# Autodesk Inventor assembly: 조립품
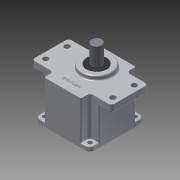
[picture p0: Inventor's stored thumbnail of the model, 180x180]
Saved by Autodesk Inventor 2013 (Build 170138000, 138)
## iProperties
Created: 2015-07
Part Number: 조립품
Document SubType Name: Assembly
Designer: user
Author: user
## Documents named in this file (12)
- C:\Users\user\Desktop\450734V1001\조립품.iam
- C:\Users\user\Desktop\450734V1001\본체.ipt
- C:\Users\user\Desktop\450734V1001\베어링 6003.ipt
- 베어링 6003.ipt
- C:\Users\user\Desktop\450734V1001\베어링 608.ipt
- 베어링 608.ipt
- C:\Users\user\Desktop\450734V1001\서브축.ipt
- C:\Users\user\Desktop\450734V1001\메인축.ipt
- C:\Users\user\Desktop\450734V1001\커버.ipt
- C:\Users\user\Desktop\450734V1001\오일실 17x32x8.ipt
- C:\Users\user\Desktop\450734V1001\오일실 8x22x7.ipt
- C:\Users\user\Desktop\450734V1001\M4x0.5x16.ipt
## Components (4 placed, 1 different names)
1. M4x0.5x12:1
2. M4x0.5x12:2
3. M4x0.5x12:3
4. M4x0.5x12:4
